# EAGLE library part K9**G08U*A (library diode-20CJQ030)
Samsung's K9**G08U*A 1G x 8 Bit / 2G x 8 Bit / 4G x 8 Bit NAND Flash Memory Description: Offered in 1G x 8bit, the K9K8G08U0A is a 8G-bit NAND Flash Memory with spare 256M-bit. Its NAND cell provides the most costeffective solution for the solid state application market. A program operation can be performed in typical 200µs on the (2K+64)Byte page and an erase operation can be performed in typical 1.5ms on a (128K+4K)Byte block. Data in the data register can be read out at 25ns(K9NBG08U5A : 50ns) cycle time per Byte. The I/O pins serve as the ports for address and data input/output as well as command input. The on-chip write controller automates all program and erase functions including pulse repetition, where required, and internal verification and margining of data. Even the write-intensive systems can take advantage of the K9K8G08U0A?s extended reliability of 100K program/erase cycles by providing ECC(Error Correcting Code) with real time mapping-out algorithm. The K9K8G08U0A is an optimum solution for large nonvolatile storage applications such as solid state file storage and other portable applications requiring non-volatility. An ultra high density solution having two 8Gb stacked with two chip selects is also available in standard TSOPI package and another ultra high density solution having two 16Gb TSOPI package stacked with four chip selects is also available in TSOPI-DSP. Features: Voltage Supply - 2.70V ~ 3.60V Organization - Memory Cell Array : (1G + 32M) - Data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
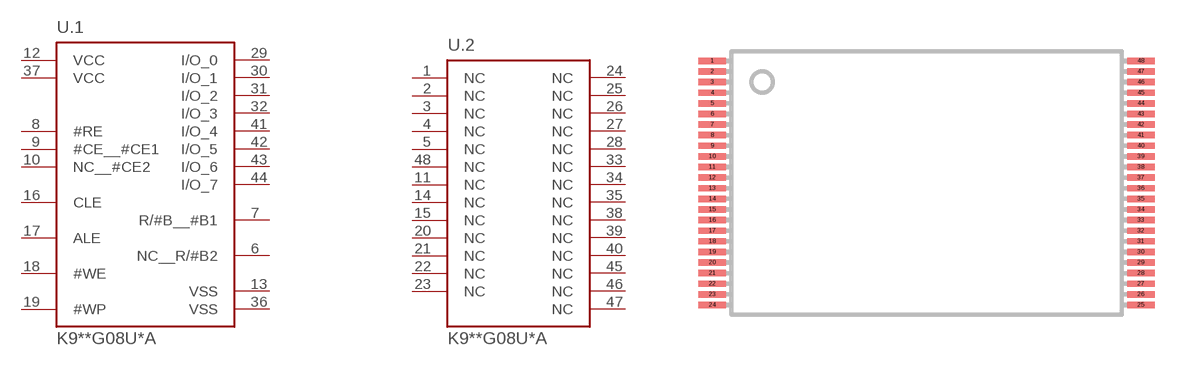
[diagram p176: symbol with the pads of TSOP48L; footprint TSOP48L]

Designator prefix U; gates .1=K9**G08U*A .2=K9**G08U*A_NC

## K9G08UA-Y  [TSOP48L]
1  .2:NC  nc
2  .2:NC  nc
3  .2:NC  nc
4  .2:NC  nc
5  .2:NC  nc
6  .1:NC__R/#B2  in
7  .1:R/#B__#B1  in
8  .1:#RE  in
9  .1:#CE__#CE1  in
10  .1:NC__#CE2  in
11  .2:NC  nc
12  .1:VCC  in
13  .1:VSS  pwr
14  .2:NC  nc
15  .2:NC  nc
16  .1:CLE  in
17  .1:ALE  in
18  .1:#WE  in
19  .1:#WP  in
20  .2:NC  nc
21  .2:NC  nc
22  .2:NC  nc
23  .2:NC  nc
24  .2:NC  nc
25  .2:NC  nc
26  .2:NC  nc
27  .2:NC  nc
28  .2:NC  nc
29  .1:I/O_0
30  .1:I/O_1
31  .1:I/O_2
32  .1:I/O_3
33  .2:NC  nc
34  .2:NC  nc
35  .2:NC  nc
36  .1:VSS  pwr
37  .1:VCC  in
38  .2:NC  nc
39  .2:NC  nc
40  .2:NC  nc
41  .1:I/O_4
42  .1:I/O_5
43  .1:I/O_6
44  .1:I/O_7
45  .2:NC  nc
46  .2:NC  nc
47  .2:NC  nc
48  .2:NC  nc

## Footprint TSOP48L (pad centres in mm)
Thin Small Outline Package Smasung's FLASH MEMORY K9WAG08U1A K9K8G08U0A K9NBG08U5A
smd 1.3 x 0.3: 1 -10.1,5.75; 2 -10.1,5.25; 3 -10.1,4.75; 4 -10.1,4.25; 5 -10.1,3.75; 6 -10.1,3.25; 7 -10.1,2.75; 8 -10.1,2.25; 9 -10.1,1.75; 10 -10.1,1.25; 11 -10.1,0.75; 12 -10.1,0.25; 13 -10.1,-0.25; 14 -10.1,-0.75; 15 -10.1,-1.25; 16 -10.1,-1.75; 17 -10.1,-2.25; 18 -10.1,-2.75; 19 -10.1,-3.25; 20 -10.1,-3.75; 21 -10.1,-4.25; 22 -10.1,-4.75; 23 -10.1,-5.25; 24 -10.1,-5.75; 25 10.1,-5.75; 26 10.1,-5.25; 27 10.1,-4.75; 28 10.1,-4.25; 29 10.1,-3.75; 30 10.1,-3.25; 31 10.1,-2.75; 32 10.1,-2.25; 33 10.1,-1.75; 34 10.1,-1.25; 35 10.1,-0.75; 36 10.1,-0.25; 37 10.1,0.25; 38 10.1,0.75; 39 10.1,1.25; 40 10.1,1.75; 41 10.1,2.25; 42 10.1,2.75; 43 10.1,3.25; 44 10.1,3.75; 45 10.1,4.25; 46 10.1,4.75; 47 10.1,5.25; 48 10.1,5.75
